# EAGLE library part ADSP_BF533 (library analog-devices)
ADSP-BF533 - Blackfin Processor for Video/Imaging Auto generated by make-symbol-device-package-bsdl.ulp Source: 33260205658992ADSP_BF533_mbga.bsdl
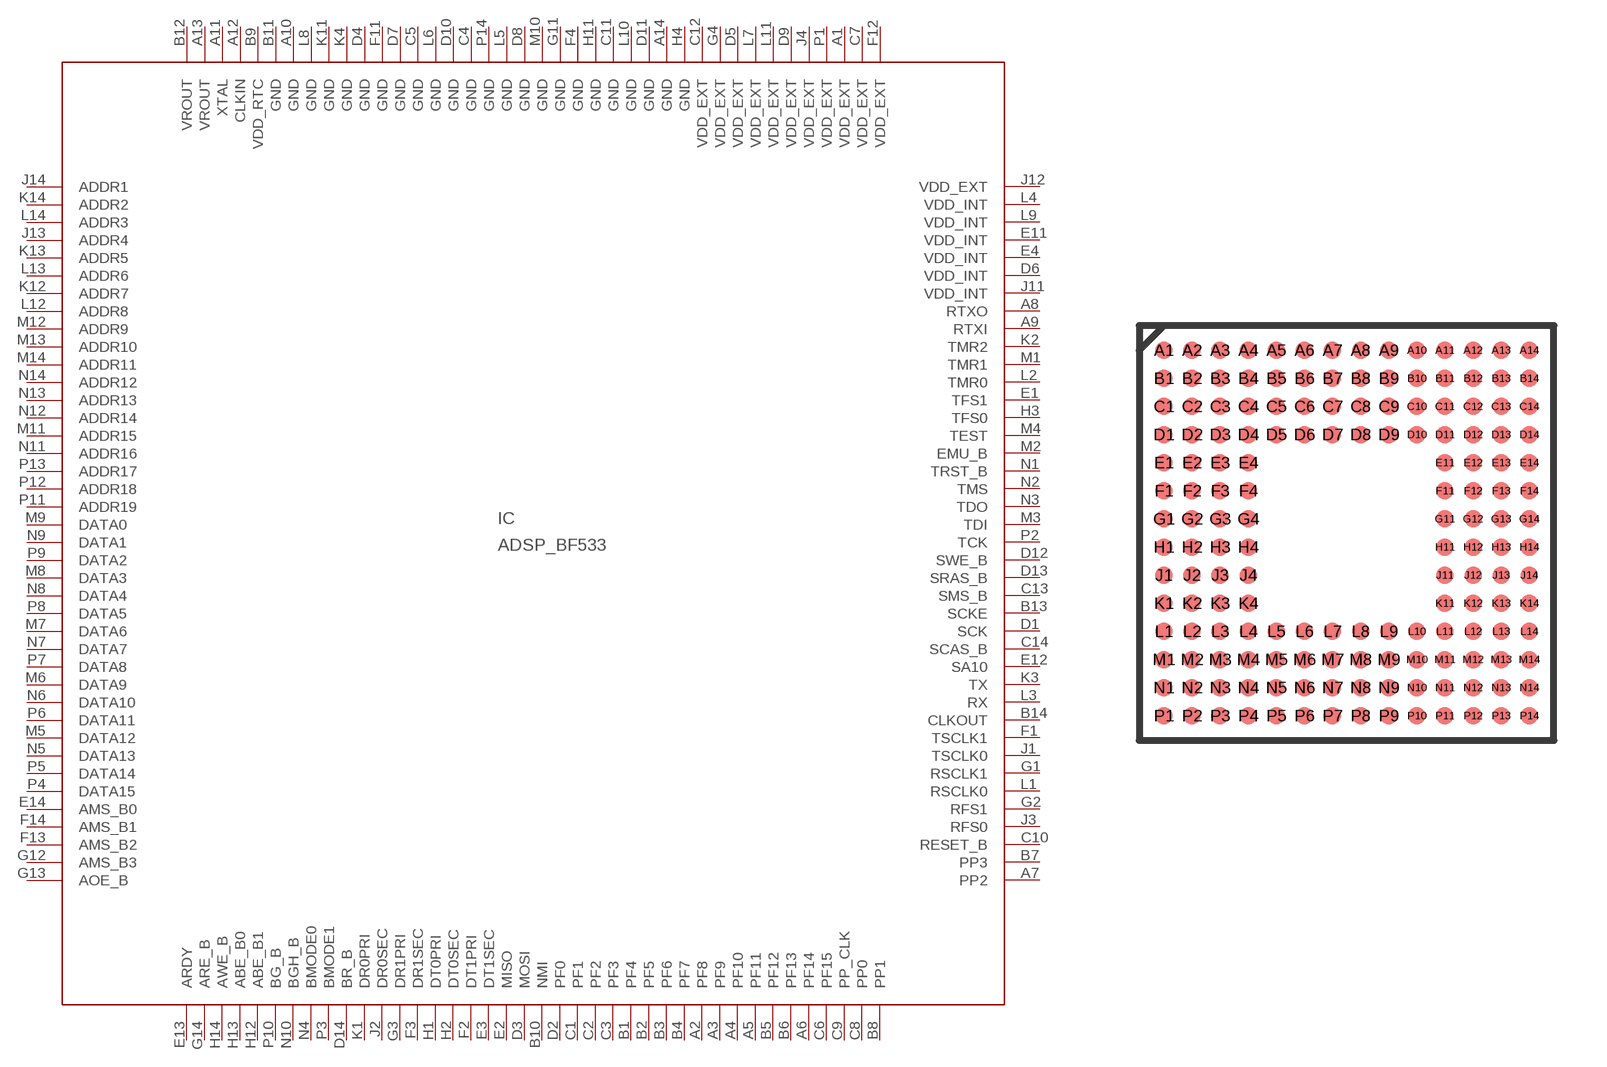
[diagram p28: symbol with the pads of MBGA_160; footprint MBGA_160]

Designator prefix IC

## ADSP_BF533 (OC_FARNELL: 1465585; OC_NEWARK: unknown)  [MBGA_160]
A1  VDD_EXT  pwr
A2  PF8
A3  PF9
A4  PF10
A5  PF11
A6  PF14
A7  PP2
A8  RTXO  pwr
A9  RTXI  pwr
A10  GND  pwr
A11  XTAL  pwr
A12  CLKIN  pwr
A13  VROUT  pwr
A14  GND  pwr
B1  PF4
B2  PF5
B3  PF6
B4  PF7
B5  PF12
B6  PF13
B7  PP3
B8  PP1
B9  VDD_RTC  pwr
B10  NMI  in
B11  GND  pwr
B12  VROUT  pwr
B13  SCKE  out
B14  CLKOUT  out
C1  PF1
C2  PF2
C3  PF3
C4  GND  pwr
C5  GND  pwr
C6  PF15
C7  VDD_EXT  pwr
C8  PP0
C9  PP_CLK  in
C10  RESET_B  in
C11  GND  pwr
C12  VDD_EXT  pwr
C13  SMS_B  out
C14  SCAS_B  out
D1  SCK
D2  PF0
D3  MOSI
D4  GND  pwr
D5  VDD_EXT  pwr
D6  VDD_INT  pwr
D7  GND  pwr
D8  GND  pwr
D9  VDD_EXT  pwr
D10  GND  pwr
D11  GND  pwr
D12  SWE_B  out
D13  SRAS_B  out
D14  BR_B  in
E1  TFS1
E2  MISO
E3  DT1SEC  out
E4  VDD_INT  pwr
E11  VDD_INT  pwr
E12  SA10  out
E13  ARDY  in
E14  AMS_B0  out
F1  TSCLK1
F2  DT1PRI  out
F3  DR1SEC  in
F4  GND  pwr
F11  GND  pwr
F12  VDD_EXT  pwr
F13  AMS_B2  out
F14  AMS_B1  out
G1  RSCLK1
G2  RFS1
G3  DR1PRI  in
G4  VDD_EXT  pwr
G11  GND  pwr
G12  AMS_B3  out
G13  AOE_B  out
G14  ARE_B  out
H1  DT0PRI  out
H2  DT0SEC  out
H3  TFS0
H4  GND  pwr
H11  GND  pwr
H12  ABE_B1  out
H13  ABE_B0  out
H14  AWE_B  out
J1  TSCLK0
J2  DR0SEC  in
J3  RFS0
J4  VDD_EXT  pwr
J11  VDD_INT  pwr
J12  VDD_EXT  pwr
J13  ADDR4  out
J14  ADDR1  out
K1  DR0PRI  in
K2  TMR2
K3  TX  hiz
K4  GND  pwr
K11  GND  pwr
K12  ADDR7  out
K13  ADDR5  out
K14  ADDR2  out
L1  RSCLK0
L2  TMR0
L3  RX  in
L4  VDD_INT  pwr
L5  GND  pwr
L6  GND  pwr
L7  VDD_EXT  pwr
L8  GND  pwr
L9  VDD_INT  pwr
L10  GND  pwr
L11  VDD_EXT  pwr
L12  ADDR8  out
L13  ADDR6  out
L14  ADDR3  out
M1  TMR1
M2  EMU_B  pwr
M3  TDI  in
M4  TEST  in
M5  DATA12
M6  DATA9
M7  DATA6
M8  DATA3
M9  DATA0
M10  GND  pwr
M11  ADDR15  out
M12  ADDR9  out
M13  ADDR10  out
M14  ADDR11  out
N1  TRST_B  in
N2  TMS  in
N3  TDO  out
N4  BMODE0  in
N5  DATA13
N6  DATA10
N7  DATA7
N8  DATA4
N9  DATA1
N10  BGH_B  hiz
N11  ADDR16  out
N12  ADDR14  out
N13  ADDR13  out
N14  ADDR12  out
P1  VDD_EXT  pwr
P2  TCK  in
P3  BMODE1  in
P4  DATA15
P5  DATA14
P6  DATA11
P7  DATA8
P8  DATA5
P9  DATA2
P10  BG_B  hiz
P11  ADDR19  out
P12  ADDR18  out
P13  ADDR17  out
P14  GND  pwr

## Footprint MBGA_160 (pad centres in mm)
MBGA 160 Auto generated by make-symbol-device-package-bsdl.ulp Rev. 8 Source: 33170285923617ADSP_BF531_mbga.bsdl
smd 0.5 x 0.5: A1 -5.2,5.2; A2 -4.4,5.2; A3 -3.6,5.2; A4 -2.8,5.2; A5 -2,5.2; A6 -1.2,5.2; A7 -0.4,5.2; A8 0.4,5.2; A9 1.2,5.2; A10 2,5.2; A11 2.8,5.2; A12 3.6,5.2; A13 4.4,5.2; A14 5.2,5.2; B1 -5.2,4.4; B2 -4.4,4.4; B3 -3.6,4.4; B4 -2.8,4.4; B5 -2,4.4; B6 -1.2,4.4; B7 -0.4,4.4; B8 0.4,4.4; B9 1.2,4.4; B10 2,4.4; B11 2.8,4.4; B12 3.6,4.4; B13 4.4,4.4; B14 5.2,4.4; C1 -5.2,3.6; C2 -4.4,3.6; C3 -3.6,3.6; C4 -2.8,3.6; C5 -2,3.6; C6 -1.2,3.6; C7 -0.4,3.6; C8 0.4,3.6; C9 1.2,3.6; C10 2,3.6; C11 2.8,3.6; C12 3.6,3.6; C13 4.4,3.6; C14 5.2,3.6; D1 -5.2,2.8; D2 -4.4,2.8; D3 -3.6,2.8; D4 -2.8,2.8; D5 -2,2.8; D6 -1.2,2.8; D7 -0.4,2.8; D8 0.4,2.8; D9 1.2,2.8; D10 2,2.8; D11 2.8,2.8; D12 3.6,2.8; D13 4.4,2.8; D14 5.2,2.8; E1 -5.2,2; E2 -4.4,2; E3 -3.6,2; E4 -2.8,2; E11 2.8,2; E12 3.6,2; E13 4.4,2; E14 5.2,2; F1 -5.2,1.2; F2 -4.4,1.2; F3 -3.6,1.2; F4 -2.8,1.2; F11 2.8,1.2; F12 3.6,1.2; F13 4.4,1.2; F14 5.2,1.2; G1 -5.2,0.4; G2 -4.4,0.4; G3 -3.6,0.4; G4 -2.8,0.4; G11 2.8,0.4; G12 3.6,0.4; G13 4.4,0.4; G14 5.2,0.4; H1 -5.2,-0.4; H2 -4.4,-0.4; H3 -3.6,-0.4; H4 -2.8,-0.4; H11 2.8,-0.4; H12 3.6,-0.4; H13 4.4,-0.4; H14 5.2,-0.4; J1 -5.2,-1.2; J2 -4.4,-1.2; J3 -3.6,-1.2; J4 -2.8,-1.2; J11 2.8,-1.2; J12 3.6,-1.2; J13 4.4,-1.2; J14 5.2,-1.2; K1 -5.2,-2; K2 -4.4,-2; K3 -3.6,-2; K4 -2.8,-2; K11 2.8,-2; K12 3.6,-2; K13 4.4,-2; K14 5.2,-2; L1 -5.2,-2.8; L2 -4.4,-2.8; L3 -3.6,-2.8; L4 -2.8,-2.8; L5 -2,-2.8; L6 -1.2,-2.8; L7 -0.4,-2.8; L8 0.4,-2.8; L9 1.2,-2.8; L10 2,-2.8; L11 2.8,-2.8; L12 3.6,-2.8; L13 4.4,-2.8; L14 5.2,-2.8; M1 -5.2,-3.6; M2 -4.4,-3.6; M3 -3.6,-3.6; M4 -2.8,-3.6; M5 -2,-3.6; M6 -1.2,-3.6; M7 -0.4,-3.6; M8 0.4,-3.6; M9 1.2,-3.6; M10 2,-3.6; M11 2.8,-3.6; M12 3.6,-3.6; M13 4.4,-3.6; M14 5.2,-3.6; N1 -5.2,-4.4; N2 -4.4,-4.4; N3 -3.6,-4.4; N4 -2.8,-4.4; N5 -2,-4.4; N6 -1.2,-4.4; N7 -0.4,-4.4; N8 0.4,-4.4; N9 1.2,-4.4; N10 2,-4.4; N11 2.8,-4.4; N12 3.6,-4.4; N13 4.4,-4.4; N14 5.2,-4.4; P1 -5.2,-5.2; P2 -4.4,-5.2; P3 -3.6,-5.2; P4 -2.8,-5.2; P5 -2,-5.2; P6 -1.2,-5.2; P7 -0.4,-5.2; P8 0.4,-5.2; P9 1.2,-5.2; P10 2,-5.2; P11 2.8,-5.2; P12 3.6,-5.2; P13 4.4,-5.2; P14 5.2,-5.2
